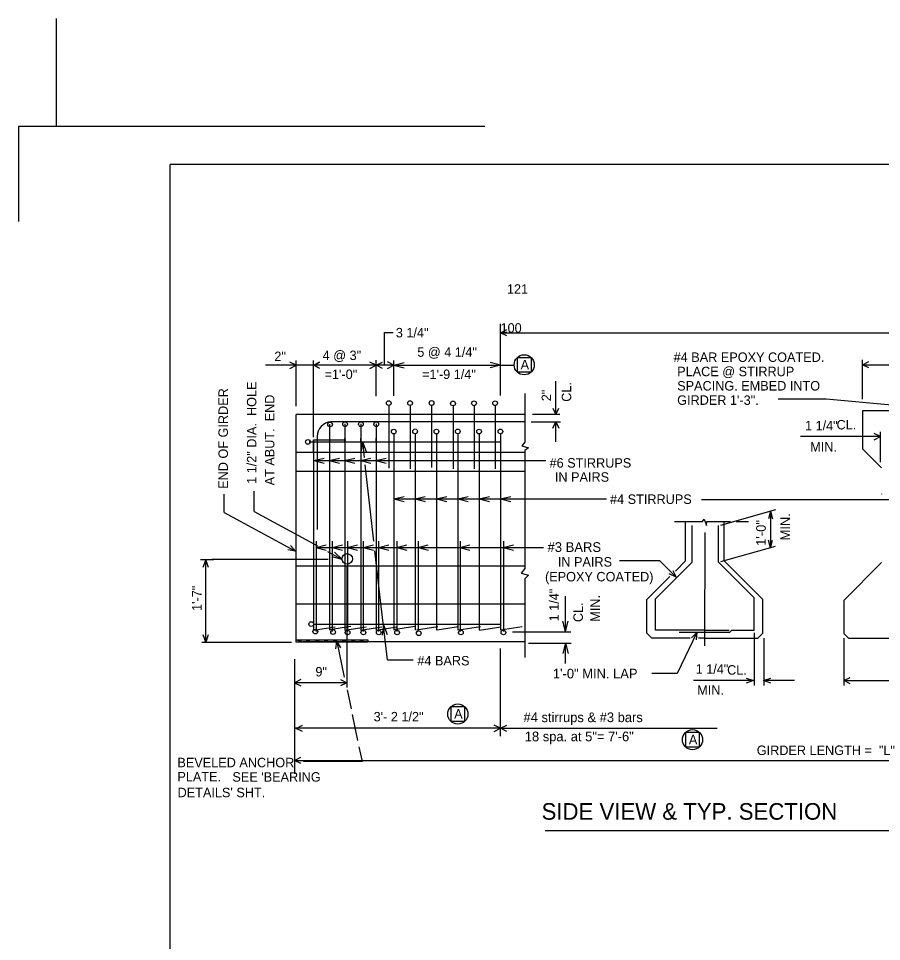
# Model space of a CAD drawing. Extents: x 1005.4 to 1102, y 2007.8 to 2074.2.
# Drawn here: x 1008.66 to 1039.02, y 2041.69 to 2074.18 of the extents above; entities that cross this region are included whole.
import ezdxf

# ---------------------------------------------------------------- set-up
doc = ezdxf.new("R2010")
doc.units = 0
for name, color, linetype in [('Level 1', 7, 'Continuous'), ('Level 2', 7, 'Continuous'), ('Level 5', 7, 'Continuous'), ('Level 6', 7, 'Continuous'), ('Level 60', 7, 'Continuous')]:
    doc.layers.add(name, color=color, linetype=linetype)

msp = doc.modelspace()

# ---------------------------------------------------------------- linework, layer by layer
at = {"layer": 'Level 1'}
for p, q in [((1025.057, 2070.374), (1008.656, 2070.374)), ((1008.656, 2070.374), (1008.656, 2067.034)), ((1013.989, 2013.041), (1013.989, 2069.04)), ((1097.657, 2069.04), (1013.989, 2069.04))]:
    msp.add_line(p, q, dxfattribs=at)
at = {"layer": 'Level 2'}
for p, q in [((1009.989, 2070.374), (1009.989, 2074.178)), ((1025.614, 2060.904), (1025.614, 2063.43)), ((1021.537, 2061.975), (1021.537, 2063.122)), ((1021.537, 2063.122), (1021.839, 2063.122)), ((1025.617, 2063.119), (1052.076, 2063.119)), ((1019.039, 2061.97), (1017.341, 2061.97)), ((1018.426, 2060.537), (1018.426, 2062.142)), ((1019.039, 2059.444), (1019.039, 2062.142)), ((1021.864, 2061.975), (1019.039, 2061.975)), ((1021.239, 2060.885), (1021.239, 2062.153)), ((1021.864, 2060.891), (1021.864, 2062.142)), ((1021.864, 2061.975), (1022.224, 2062.065)), ((1021.864, 2061.975), (1026.089, 2061.975)), ((1021.864, 2061.975), (1022.224, 2061.885)), ((1025.614, 2061.975), (1025.254, 2062.065)), ((1025.614, 2061.975), (1025.254, 2062.065)), ((1025.614, 2061.975), (1025.254, 2061.885)), ((1025.614, 2061.975), (1025.254, 2061.885)), ((1026.698, 2062.239), (1026.198, 2062.239)), ((1026.198, 2062.239), (1026.198, 2061.739)), ((1026.698, 2061.739), (1026.698, 2062.239)), ((1038.352, 2060.774), (1038.352, 2062.159)), ((1038.352, 2061.992), (1041.019, 2061.992)), ((1026.198, 2061.739), (1026.698, 2061.739)), ((1026.202, 2061.739), (1026.202, 2061.739)), ((1027.559, 2060.236), (1027.559, 2061.418)), ((1026.466, 2060.978), (1026.466, 2059.266)), ((1021.679, 2060.562), (1021.679, 2058.351)), ((1022.434, 2060.543), (1022.434, 2058.332)), ((1023.19, 2060.581), (1023.19, 2058.37)), ((1023.946, 2060.543), (1023.946, 2058.332)), ((1024.683, 2060.543), (1024.683, 2058.332)), ((1025.42, 2060.543), (1025.42, 2058.332)), ((1041.019, 2060.366), (1038.352, 2060.366)), ((1038.352, 2060.366), (1038.352, 2059.033)), ((1026.466, 2060.236), (1018.426, 2060.236)), ((1018.426, 2052.307), (1018.426, 2060.236)), ((1026.735, 2060.247), (1027.702, 2060.247)), ((1019.599, 2059.895), (1019.599, 2053.827)), ((1026.466, 2059.986), (1019.644, 2059.986)), ((1020.14, 2059.905), (1020.14, 2052.647)), ((1020.696, 2059.905), (1020.696, 2052.647)), ((1021.239, 2059.905), (1021.239, 2052.647)), ((1026.689, 2059.986), (1027.725, 2059.986)), ((1027.559, 2059.277), (1027.559, 2059.986)), ((1019.158, 2059.468), (1019.158, 2056.196)), ((1020.14, 2059.25), (1020.14, 2059.411)), ((1020.696, 2059.25), (1020.696, 2059.411)), ((1021.239, 2059.25), (1021.239, 2059.411)), ((1021.864, 2059.541), (1021.864, 2052.647)), ((1022.614, 2059.56), (1022.614, 2052.647)), ((1023.364, 2059.56), (1023.364, 2052.647)), ((1024.114, 2059.57), (1024.114, 2052.647)), ((1024.864, 2059.551), (1024.864, 2052.647)), ((1025.614, 2059.56), (1025.614, 2052.647)), ((1038.985, 2059.463), (1036.164, 2059.463)), ((1038.985, 2058.567), (1038.985, 2059.63)), ((1018.885, 2059.28), (1025.614, 2059.28)), ((1019.039, 2058.922), (1019.039, 2059.35)), ((1019.039, 2059.347), (1020.169, 2059.347)), ((1019.039, 2059.347), (1019.039, 2052.647)), ((1020.754, 2059.28), (1020.705, 2058.912)), ((1020.754, 2059.28), (1020.884, 2058.932)), ((1020.754, 2059.28), (1020.817, 2058.725)), ((1026.466, 2059.266), (1026.367, 2059.134)), ((1026.367, 2059.134), (1026.598, 2059.068)), ((1026.598, 2059.068), (1026.466, 2058.97)), ((1037.277, 2059.147), (1037.277, 2059.147)), ((1026.466, 2058.903), (1018.426, 2058.903)), ((1026.466, 2058.97), (1026.466, 2054.82)), ((1038.352, 2059.033), (1039.02, 2058.365)), ((1019.048, 2058.616), (1019.408, 2058.706)), ((1019.048, 2058.616), (1019.76, 2058.616)), ((1019.048, 2058.616), (1019.408, 2058.526)), ((1019.59, 2058.616), (1019.95, 2058.706)), ((1019.59, 2058.616), (1019.95, 2058.526)), ((1019.759, 2058.616), (1020.47, 2058.616)), ((1020.129, 2058.616), (1020.489, 2058.706)), ((1020.129, 2058.616), (1020.489, 2058.526)), ((1020.445, 2058.616), (1027.209, 2058.616)), ((1020.688, 2058.616), (1021.048, 2058.706)), ((1020.688, 2058.616), (1021.048, 2058.526)), ((1021.156, 2055.779), (1020.847, 2058.47)), ((1021.229, 2058.616), (1021.589, 2058.706)), ((1021.229, 2058.616), (1021.589, 2058.526)), ((1026.466, 2058.235), (1018.426, 2058.235)), ((1015.896, 2056.792), (1015.896, 2057.432)), ((1039.014, 2057.449), (1039.014, 2057.434)), ((1021.864, 2057.269), (1022.224, 2057.359)), ((1021.864, 2057.269), (1022.617, 2057.269)), ((1021.864, 2057.269), (1022.224, 2057.179)), ((1022.605, 2057.269), (1022.965, 2057.359)), ((1022.605, 2057.269), (1022.965, 2057.179)), ((1022.617, 2057.269), (1023.366, 2057.269)), ((1023.366, 2057.269), (1023.726, 2057.359)), ((1023.366, 2057.269), (1024.114, 2057.269)), ((1023.366, 2057.269), (1023.726, 2057.179)), ((1024.114, 2057.269), (1024.474, 2057.359)), ((1024.114, 2057.269), (1024.863, 2057.269)), ((1024.114, 2057.269), (1024.474, 2057.179)), ((1024.863, 2057.269), (1025.223, 2057.359)), ((1024.863, 2057.269), (1025.636, 2057.269)), ((1024.863, 2057.269), (1025.223, 2057.179)), ((1025.614, 2057.269), (1025.974, 2057.359)), ((1025.614, 2057.269), (1025.974, 2057.179)), ((1025.636, 2057.269), (1029.34, 2057.269)), ((1032.684, 2057.243), (1039.307, 2057.243)), ((1015.896, 2056.792), (1018.401, 2055.433)), ((1033.366, 2056.348), (1035.293, 2056.891)), ((1035.109, 2056.843), (1035.041, 2056.571)), ((1035.109, 2056.843), (1035.177, 2056.571)), ((1035.111, 2056.85), (1035.111, 2055.567)), ((1031.739, 2056.472), (1032.722, 2056.472)), ((1032.124, 2055.087), (1032.124, 2056.472)), ((1032.722, 2056.472), (1032.774, 2056.559)), ((1032.774, 2056.559), (1032.854, 2056.33)), ((1032.854, 2056.33), (1032.866, 2056.472)), ((1032.866, 2056.472), (1033.709, 2056.472)), ((1033.482, 2055.087), (1033.482, 2056.472)), ((1033.903, 2056.472), (1034.332, 2056.472)), ((1032.353, 2055.04), (1032.353, 2056.329)), ((1033.283, 2055.04), (1033.283, 2056.329)), ((1032.803, 2052.103), (1032.818, 2056.089)), ((1035.109, 2055.544), (1035.041, 2055.816)), ((1035.109, 2055.544), (1035.177, 2055.816)), ((1019.117, 2055.559), (1019.477, 2055.649)), ((1019.117, 2055.559), (1019.477, 2055.469)), ((1019.123, 2055.784), (1019.123, 2052.602)), ((1019.123, 2055.559), (1019.884, 2055.559)), ((1019.69, 2055.559), (1020.05, 2055.649)), ((1019.69, 2055.559), (1020.05, 2055.469)), ((1019.693, 2055.784), (1019.693, 2052.602)), ((1019.884, 2055.559), (1020.595, 2055.559)), ((1020.22, 2055.559), (1020.58, 2055.649)), ((1020.22, 2055.559), (1020.58, 2055.469)), ((1020.225, 2055.784), (1020.225, 2052.602)), ((1020.595, 2055.559), (1022.005, 2055.559)), ((1020.78, 2055.559), (1021.14, 2055.649)), ((1020.78, 2055.559), (1021.14, 2055.469)), ((1020.782, 2055.784), (1020.782, 2052.602)), ((1021.32, 2055.559), (1021.68, 2055.649)), ((1021.32, 2055.559), (1021.68, 2055.469)), ((1021.324, 2055.784), (1021.324, 2052.602)), ((1021.963, 2055.559), (1022.323, 2055.649)), ((1021.963, 2055.559), (1022.323, 2055.469)), ((1021.968, 2055.784), (1021.968, 2052.602)), ((1022.005, 2055.559), (1022.754, 2055.559)), ((1022.711, 2055.559), (1023.071, 2055.649)), ((1022.711, 2055.559), (1023.071, 2055.469)), ((1022.716, 2055.784), (1022.716, 2052.602)), ((1022.754, 2055.559), (1024.189, 2055.559)), ((1024.175, 2055.559), (1024.535, 2055.649)), ((1024.175, 2055.559), (1024.535, 2055.469)), ((1024.189, 2055.784), (1024.189, 2052.602)), ((1024.189, 2055.559), (1025.711, 2055.559)), ((1025.711, 2055.559), (1026.071, 2055.649)), ((1025.711, 2055.559), (1027.129, 2055.559)), ((1025.711, 2055.559), (1026.071, 2055.469)), ((1025.724, 2055.784), (1025.724, 2052.602)), ((1033.364, 2055.063), (1035.292, 2055.606)), ((1021.408, 2053.583), (1021.195, 2055.44)), ((1026.466, 2054.902), (1018.426, 2054.902)), ((1026.466, 2054.82), (1026.334, 2054.656)), ((1031.215, 2055.084), (1029.798, 2055.084)), ((1031.065, 2053.752), (1032.353, 2055.04)), ((1031.789, 2054.511), (1031.215, 2055.084)), ((1031.764, 2054.727), (1032.124, 2055.087)), ((1034.54, 2053.782), (1033.283, 2055.04)), ((1034.839, 2053.729), (1033.482, 2055.087)), ((1039.02, 2055.031), (1037.686, 2053.698)), ((1026.334, 2054.656), (1026.598, 2054.59)), ((1026.598, 2054.59), (1026.466, 2054.458)), ((1030.766, 2053.729), (1031.575, 2054.538)), ((1026.466, 2054.458), (1026.466, 2051.69)), ((1021.636, 2051.601), (1021.372, 2053.896)), ((1026.466, 2053.568), (1018.426, 2053.568)), ((1019.599, 2053.827), (1019.599, 2052.647)), ((1027.901, 2052.603), (1027.901, 2053.841)), ((1030.766, 2052.541), (1030.766, 2053.729)), ((1031.065, 2052.651), (1031.065, 2053.752)), ((1034.54, 2052.651), (1034.54, 2053.782)), ((1034.839, 2052.541), (1034.839, 2053.729)), ((1037.686, 2053.698), (1037.686, 2052.531)), ((1027.901, 2052.603), (1027.811, 2052.963)), ((1027.901, 2052.603), (1027.991, 2052.963)), ((1019.039, 2052.863), (1025.614, 2052.863)), ((1019.039, 2052.647), (1019.792, 2052.768)), ((1019.599, 2052.674), (1020.352, 2052.795)), ((1020.131, 2052.647), (1020.884, 2052.768)), ((1020.687, 2052.647), (1021.441, 2052.768)), ((1021.23, 2052.647), (1021.983, 2052.768)), ((1021.493, 2052.842), (1021.447, 2052.474)), ((1021.493, 2052.842), (1021.626, 2052.495)), ((1021.85, 2052.674), (1022.603, 2052.795)), ((1022.657, 2052.661), (1023.411, 2052.782)), ((1023.384, 2052.661), (1024.137, 2052.782)), ((1024.151, 2052.661), (1024.904, 2052.782)), ((1024.877, 2052.647), (1025.63, 2052.768)), ((1025.617, 2052.661), (1026.37, 2052.782)), ((1026.04, 2052.595), (1028.087, 2052.595)), ((1032.804, 2052.651), (1031.065, 2052.651)), ((1032.524, 2052.569), (1031.825, 2051.128)), ((1031.892, 2052.582), (1033.685, 2052.582)), ((1032.801, 2052.651), (1033.651, 2052.651)), ((1033.685, 2052.582), (1033.755, 2052.651)), ((1033.755, 2052.651), (1034.54, 2052.651)), ((1034.54, 2052.554), (1034.54, 2050.706)), ((1018.426, 2052.307), (1018.672, 2052.234)), ((1026.466, 2052.234), (1018.672, 2052.234)), ((1030.935, 2052.369), (1030.766, 2052.541)), ((1032.282, 2052.369), (1030.935, 2052.369)), ((1032.803, 2052.369), (1032.575, 2052.369)), ((1032.803, 2052.369), (1032.803, 2052.369)), ((1032.803, 2052.369), (1032.803, 2052.369)), ((1032.803, 2052.369), (1032.803, 2052.369)), ((1032.803, 2052.369), (1032.803, 2052.369)), ((1032.803, 2052.369), (1032.803, 2052.369)), ((1032.803, 2052.369), (1034.67, 2052.369)), ((1032.803, 2052.369), (1032.803, 2052.369)), ((1032.803, 2052.369), (1032.803, 2052.369)), ((1032.803, 2052.369), (1032.803, 2052.369)), ((1034.67, 2052.369), (1034.839, 2052.541)), ((1034.878, 2052.365), (1034.878, 2050.706)), ((1037.686, 2052.531), (1037.853, 2052.365)), ((1037.686, 2052.365), (1037.686, 2050.706)), ((1037.851, 2052.364), (1041.518, 2052.364)), ((1025.614, 2048.921), (1025.614, 2052.008)), ((1026.597, 2052.193), (1028.103, 2052.193)), ((1027.901, 2052.187), (1027.811, 2051.827)), ((1027.901, 2051.479), (1027.901, 2052.187)), ((1027.901, 2052.187), (1027.991, 2051.827)), ((1018.361, 2051.625), (1018.361, 2047.594)), ((1021.636, 2051.601), (1022.542, 2051.601)), ((1031.825, 2051.128), (1030.932, 2051.128)), ((1034.51, 2050.873), (1032.405, 2050.873)), ((1035.952, 2050.873), (1034.863, 2050.873)), ((1037.686, 2050.873), (1041.685, 2050.873)), ((1024.361, 2049.947), (1023.861, 2049.947)), ((1023.861, 2049.947), (1023.861, 2049.447)), ((1024.361, 2049.447), (1024.361, 2049.947)), ((1023.861, 2049.447), (1024.361, 2049.447)), ((1023.866, 2049.447), (1023.866, 2049.447)), ((1025.614, 2049.196), (1018.361, 2049.196)), ((1025.614, 2049.196), (1033.237, 2049.196)), ((1032.617, 2049.044), (1032.117, 2049.044)), ((1032.117, 2049.044), (1032.117, 2048.544)), ((1032.617, 2048.544), (1032.617, 2049.044)), ((1032.117, 2048.544), (1032.617, 2048.544)), ((1032.121, 2048.544), (1032.121, 2048.544)), ((1018.361, 2048.066), (1057.695, 2048.066)), ((1027.181, 2045.596), (1043.723, 2045.596))]:
    msp.add_line(p, q, dxfattribs=at)
for points in [[(1025.836, 2063.008), (1025.614, 2063.119), (1025.836, 2063.23)], [(1018.201, 2061.859), (1018.423, 2061.971), (1018.201, 2062.082)], [(1019.261, 2061.864), (1019.039, 2061.975), (1019.261, 2062.087)], [(1019.263, 2061.859), (1019.041, 2061.971), (1019.263, 2062.082)], [(1021.016, 2061.864), (1021.238, 2061.975), (1021.016, 2062.086)], [(1021.461, 2061.864), (1021.239, 2061.975), (1021.461, 2062.086)], [(1021.641, 2061.864), (1021.864, 2061.975), (1021.641, 2062.087)], [(1021.869, 2061.973), (1021.864, 2061.975), (1021.869, 2061.978)], [(1025.608, 2061.973), (1025.614, 2061.975), (1025.608, 2061.978)], [(1038.574, 2061.881), (1038.352, 2061.992), (1038.574, 2062.103)], [(1039.381, 2060.573), (1037.064, 2060.774), (1035.377, 2060.774)], [(1027.448, 2060.458), (1027.559, 2060.236), (1027.67, 2060.458)], [(1027.448, 2059.764), (1027.559, 2059.986), (1027.67, 2059.764)], [(1038.762, 2059.352), (1038.985, 2059.463), (1038.762, 2059.574)], [(1018.22, 2055.631), (1018.401, 2055.433), (1018.137, 2055.477)], [(1031.672, 2054.752), (1031.789, 2054.511), (1031.548, 2054.628)], [(1032.335, 2052.379), (1032.524, 2052.569), (1032.493, 2052.303)], [(1034.257, 2050.96), (1034.51, 2050.873), (1034.257, 2050.785)], [(1035.117, 2050.785), (1034.863, 2050.873), (1035.117, 2050.96)], [(1037.909, 2050.762), (1037.686, 2050.873), (1037.909, 2050.984)], [(1018.648, 2049.081), (1018.426, 2049.192), (1018.648, 2049.303)], [(1025.39, 2049.084), (1025.612, 2049.195), (1025.39, 2049.306)], [(1025.837, 2049.084), (1025.614, 2049.195), (1025.837, 2049.306)], [(1018.584, 2047.955), (1018.361, 2048.066), (1018.584, 2048.178)]]:
    msp.add_lwpolyline(points, dxfattribs=at)
for centre, radius in [((1026.448, 2061.989), 0.354), ((1021.68, 2060.641), 0.0833), ((1022.431, 2060.64), 0.0833), ((1023.186, 2060.644), 0.0833), ((1023.942, 2060.627), 0.0833), ((1024.681, 2060.633), 0.0833), ((1025.421, 2060.637), 0.0833), ((1019.617, 2059.891), 0.0833), ((1020.145, 2059.899), 0.0833), ((1020.701, 2059.899), 0.0833), ((1021.243, 2059.899), 0.0833), ((1021.859, 2059.637), 0.0833), ((1022.609, 2059.646), 0.0833), ((1023.359, 2059.64), 0.0833), ((1024.109, 2059.642), 0.0833), ((1024.859, 2059.638), 0.0833), ((1025.609, 2059.642), 0.0833), ((1018.837, 2059.273), 0.0833), ((1018.953, 2052.863), 0.0833), ((1019.099, 2052.599), 0.0833), ((1019.724, 2052.584), 0.0833), ((1020.232, 2052.569), 0.0833), ((1020.788, 2052.569), 0.0833), ((1021.33, 2052.569), 0.0833), ((1021.974, 2052.569), 0.0833), ((1022.737, 2052.54), 0.0833), ((1024.218, 2052.569), 0.0833), ((1025.715, 2052.569), 0.0833), ((1024.111, 2049.697), 0.354), ((1032.367, 2048.794), 0.354)]:
    msp.add_circle(centre, radius, dxfattribs=at)
msp.add_arc((1019.708, 2059.44), 0.55, 96.657, 177.0425, dxfattribs=at)
at = {"layer": 'Level 5'}
for p, q in [((1016.949, 2056.82), (1016.949, 2057.543)), ((1016.949, 2056.82), (1019.176, 2055.613)), ((1019.531, 2055.421), (1020.047, 2055.141)), ((1020.047, 2055.141), (1019.688, 2055.233)), ((1020.047, 2055.141), (1019.773, 2055.391)), ((1015.065, 2055.136), (1015.511, 2055.136)), ((1015.245, 2052.225), (1015.245, 2055.116)), ((1019.548, 2055.136), (1015.453, 2055.136)), ((1020.204, 2054.903), (1020.204, 2050.634)), ((1018.255, 2052.22), (1015.11, 2052.22)), ((1020.204, 2050.8), (1018.37, 2050.8))]:
    msp.add_line(p, q, dxfattribs=at)
for points in [[(1015.158, 2054.862), (1015.245, 2055.116), (1015.333, 2054.862)], [(1015.158, 2054.862), (1015.245, 2055.116), (1015.333, 2054.862)], [(1015.333, 2052.479), (1015.245, 2052.225), (1015.158, 2052.479)], [(1018.593, 2050.911), (1018.37, 2050.8), (1018.593, 2050.689)], [(1019.981, 2050.911), (1020.204, 2050.8), (1019.981, 2050.689)]]:
    msp.add_lwpolyline(points, dxfattribs=at)
msp.add_circle((1020.221, 2055.158), 0.186, dxfattribs=at)
at = {"layer": 'Level 6'}
for p, q in [((1018.726, 2052.307), (1018.972, 2052.234)), ((1019.057, 2052.307), (1019.304, 2052.234)), ((1019.366, 2052.307), (1019.612, 2052.234)), ((1019.677, 2052.307), (1019.923, 2052.234)), ((1019.85, 2052.253), (1020.119, 2050.997)), ((1019.994, 2052.307), (1020.241, 2052.234)), ((1020.323, 2052.307), (1020.569, 2052.234)), ((1020.623, 2052.307), (1020.869, 2052.234)), ((1020.215, 2050.552), (1020.359, 2049.883)), ((1020.599, 2048.761), (1020.401, 2049.684)), ((1020.756, 2048.032), (1020.646, 2048.542)), ((1020.756, 2048.032), (1018.688, 2048.032))]:
    msp.add_line(p, q, dxfattribs=at)
msp.add_lwpolyline([(1018.424, 2052.307), (1020.946, 2052.307), (1020.946, 2052.231), (1018.424, 2052.231)], close=True, dxfattribs=at)
msp.add_lwpolyline([(1019.817, 2051.987), (1019.85, 2052.253), (1019.989, 2052.023)], dxfattribs=at)

# ---------------------------------------------------------------- texts
at = {"layer": 'Level 2'}
for s, height, p in [('3 1/4"', 0.3333, (1021.931, 2062.953)), ('5 @ 4 1/4"', 0.3333, (1022.686, 2062.27)), ('2"', 0.3333, (1017.657, 2062.12)), ('4 @ 3" ', 0.3333, (1019.356, 2062.155)), ('#4 BAR EPOXY COATED. ', 0.33333, (1031.704, 2062.09)), ('3\'-9"', 0.00833, (1021.889, 2061.98)), ('A', 0.333, (1026.32, 2061.829)), ('=1\'-0"', 0.3333, (1019.424, 2061.488)), ('=1\'-9 1/4"', 0.3333, (1022.854, 2061.488)), (' PLACE @ STIRRUP', 0.33333, (1031.704, 2061.587)), (' SPACING. EMBED INTO ', 0.33333, (1031.704, 2061.083)), (' GIRDER 1\'-3".', 0.33333, (1031.704, 2060.579)), ('1 1/4"', 0.3333, (1036.324, 2059.681)), ('CL.', 0.3333, (1037.433, 2059.714)), ('CL.', 0.3333, (1037.433, 2059.714)), ('MIN.', 0.3333, (1036.508, 2058.934)), ('#6 STIRRUPS', 0.33333, (1027.339, 2058.369)), ('IN PAIRS', 0.3333, (1027.526, 2057.873)), ('#4 STIRRUPS', 0.33333, (1029.466, 2057.092)), ('#3 BARS', 0.3423, (1027.268, 2055.402)), ('IN PAIRS', 0.3333, (1027.629, 2054.887)), ('(EPOXY COATED)', 0.33333, (1027.179, 2054.365)), ('#4 BARS', 0.3333, (1022.688, 2051.408)), ('1\'-0" MIN. LAP', 0.34001, (1027.456, 2050.951)), ('1 1/4"', 0.3333, (1032.478, 2051.116)), ('CL.', 0.3333, (1033.585, 2051.083)), ('MIN.', 0.3333, (1032.534, 2050.375)), ('3\'- 2 1/2"', 0.3333, (1021.15, 2049.438)), ('A', 0.333, (1023.983, 2049.537)), ('#4 stirrups & #3 bars', 0.34001, (1026.423, 2049.412)), ('18 spa. at 5"= 7\'-6"', 0.34001, (1026.467, 2048.738)), ('A', 0.333, (1032.239, 2048.633)), ('GIRDER LENGTH =  "L"', 0.33333, (1034.628, 2048.255)), (' SIDE VIEW & TYP. SECTION', 0.58333, (1026.841, 2045.978))]:
    msp.add_text(s, height=height, dxfattribs=at).set_placement(p)
for s, height, p in [('CL.', 0.3333, (1028.1, 2060.686)), ('END OF GIRDER', 0.33333, (1016.024, 2057.624)), ('2"', 0.3333, (1027.392, 2060.707)), ('1\'-0"', 0.34, (1034.946, 2055.618)), ('MIN.', 0.34, (1035.798, 2055.807)), ('1 1/4"', 0.3333, (1027.663, 2052.959)), ('MIN.', 0.3333, (1029.11, 2052.946)), ('CL.', 0.3333, (1028.511, 2052.934))]:
    msp.add_text(s, height=height, rotation=90, dxfattribs=at).set_placement(p)
at = {"layer": 'Level 5'}
for s, height, p in [('1 1/2" DIA.  HOLE', 0.33333, (1017.026, 2057.797)), ('AT ABUT.  END', 0.33333, (1017.659, 2057.745)), ('1\'-7"', 0.3333, (1015.096, 2053.326))]:
    msp.add_text(s, height=height, rotation=90, dxfattribs=at).set_placement(p)
msp.add_text('9"', height=0.3333, dxfattribs=at).set_placement((1019.102, 2051.021))
at = {"layer": 'Level 6'}
for s, height, p in [('BEVELED ANCHOR', 0.33333, (1014.247, 2047.824)), ('PLATE.', 0.3333, (1014.247, 2047.324)), ("SEE 'BEARING", 0.33333, (1016.181, 2047.317)), ("DETAILS' SHT.", 0.33333, (1014.254, 2046.769))]:
    msp.add_text(s, height=height, dxfattribs=at).set_placement(p)
at = {"layer": 'Level 60'}
for s, p in [('121', (1025.84, 2064.489)), ('100', (1025.614, 2063.119))]:
    msp.add_text(s, height=0.3333, dxfattribs=at).set_placement(p)

doc.saveas('drawing.dxf')
